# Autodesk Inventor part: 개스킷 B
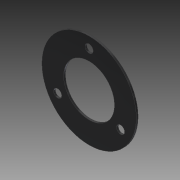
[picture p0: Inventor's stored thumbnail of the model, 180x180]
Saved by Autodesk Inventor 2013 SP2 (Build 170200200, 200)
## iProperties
Created: 2020-04
Part Number: 개스킷 B
Material: 고무
Document SubType Name: Modeling
Designer: mduedu
Density: 0.93 g/cm^3
Mass: 1.35803 g
Surface Area: 32.1424 cm^2
Volume: 1.46025 cm^3
Author: mduedu
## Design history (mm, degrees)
sketch "스케치1"
  geometry: C1 r 26 at (0, 0); 1 further point
  constraints: 1 centre point, 1 coincident
  dimensions: "d0" = 52 diameter of C1
extrude "돌출1" new body sketch "스케치1" distance "d1" = 1; taper "d2" = 0 deg
sketch "스케치3" dims "d6" = 40
  geometry: 3 further points
  constraints: 2 vertical alignment, 1 coincident, 2 other
hole "구멍1" sketch "스케치3" at (0, 20) diameter "d7" = 4.5; stored, may be unused: countersink angle "d11" = 90 deg, drill point angle "d13" = 118 deg; dims "d8" = 6, "d9" = 4, "d10" = 2, "d12" = 8
sketch "스케치4"
  geometry: C1 r 14 at (0, 0); 1 further point
  constraints: 1 centre point, 1 coincident
  dimensions: "d17" = 28 diameter of C1
extrude "돌출3" cut sketch "스케치4" stored distance "d18" = 1; taper "d19" = 0 deg
node "솔리드1"
pattern_circular "원형 패턴1" dims angle "d15" = 360 deg
